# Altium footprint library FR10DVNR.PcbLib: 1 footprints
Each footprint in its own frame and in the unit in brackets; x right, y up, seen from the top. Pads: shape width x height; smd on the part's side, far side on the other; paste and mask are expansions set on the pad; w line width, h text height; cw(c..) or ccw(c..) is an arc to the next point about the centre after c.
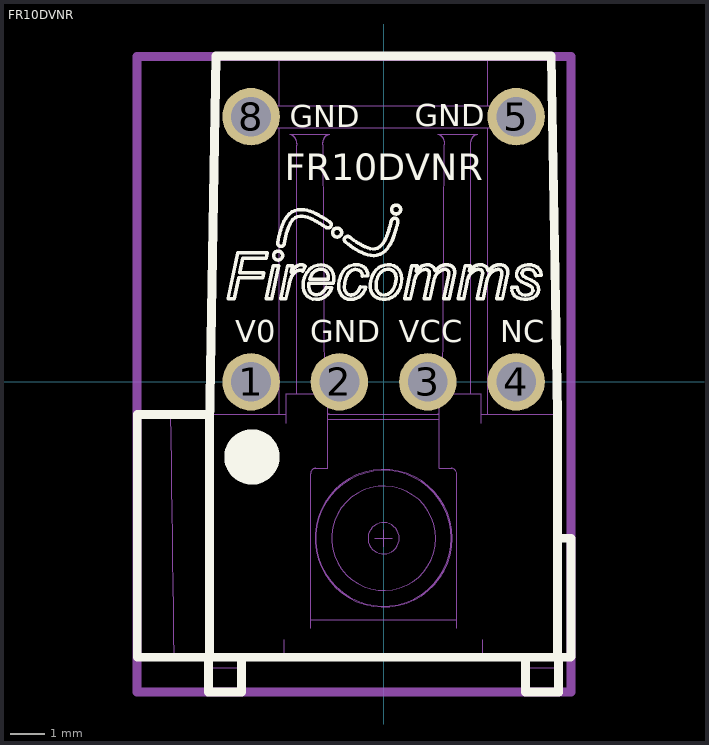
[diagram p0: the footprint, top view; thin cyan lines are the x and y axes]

## FR10DVNR [mil] "Non-Inverting RedLink® 10 MBd Receiver Vertical"
height 744.09
pads (6):
  round 65 hole 45: 1(-150,0) 2(-50,0) 3(50,0) 4(150,0) 5(150,300) 8(-150,300)
Top Overlay:
  drawing of 818 lines, arcs and shapes, not listed
  text "FR10DVNR" at -112,228 h30
  text "GND" at 35,289 h25
  text "GND" at -106,288 h25
  text "NC" at 132,45 h25
  text "VCC" at 17,45 h25
  text "GND" at -83,45 h25
  text "V0" at -168,45 h25
Mechanical 2:
  lines w10: -279,-351 -279,368 212,368 212,-351 -279,-351
Mechanical 19:
  drawing of 829 lines, arcs and shapes, not listed
3D body "Vertical Redlink Connector.stp": height 745.89, standoff -128.11, extent -278.74,-354.01 211.81,365.67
